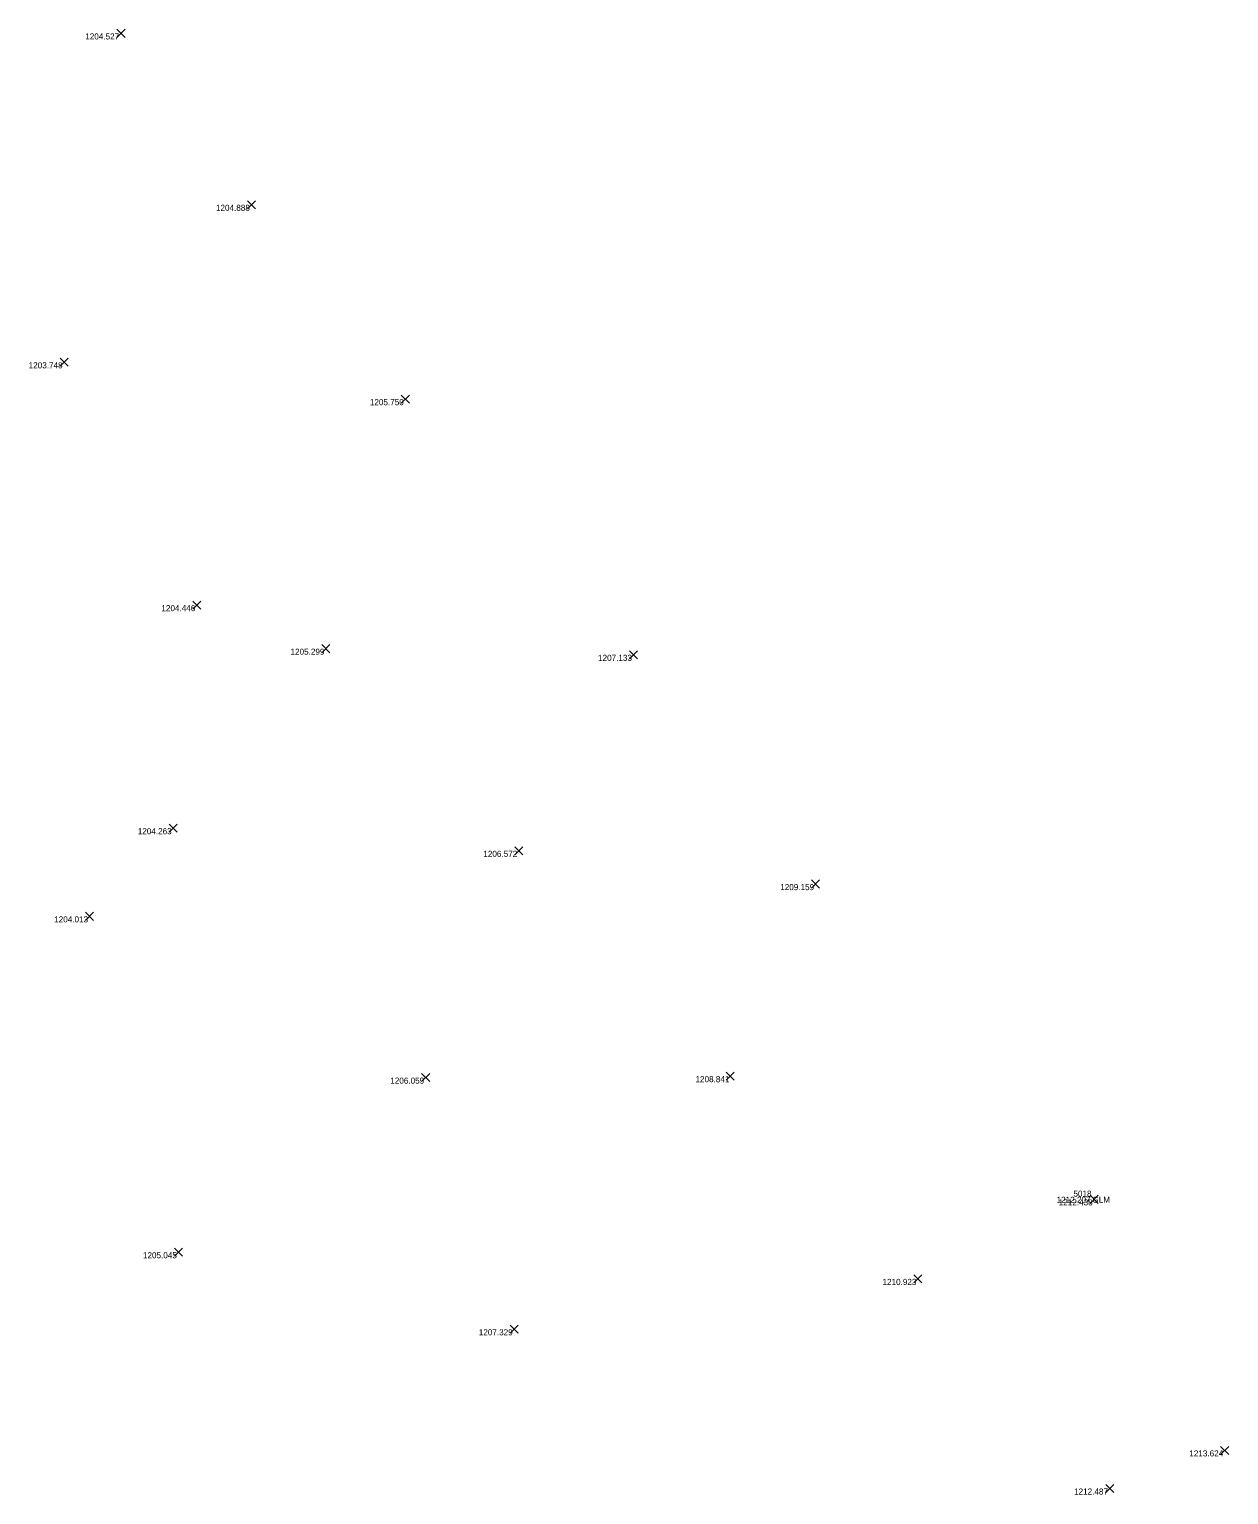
# Model space of a CAD drawing. Extents: x 2044997 to 2050342, y 455233 to 458054.
# Drawn here: x 2047746 to 2047943.2, y 457091.9 to 457332.8 of the extents above; entities that cross this region are included whole.
import ezdxf

# ---------------------------------------------------------------- set-up
doc = ezdxf.new("R2010")
doc.units = 0
for name, color, linetype in [('SV_X_Random_Point', 7, 'Continuous'), ('SV_X_Text_Comment', 7, 'Continuous'), ('SV_X_Text_Elevation', 7, 'Continuous'), ('SV_X_Text_Name', 7, 'Continuous')]:
    doc.layers.add(name, color=color, linetype=linetype)

msp = doc.modelspace()

# ---------------------------------------------------------------- linework, layer by layer
at = {"layer": 'SV_X_Random_Point'}
for p, q in [((2047760.38, 457331.47), (2047761.71, 457332.8)), ((2047760.38, 457332.8), (2047761.71, 457331.47)), ((2047781.82, 457303.29), (2047783.15, 457304.63)), ((2047781.82, 457304.63), (2047783.15, 457303.29)), ((2047751.03, 457277.4), (2047752.36, 457278.73)), ((2047751.03, 457278.73), (2047752.36, 457277.4)), ((2047807.12, 457271.34), (2047808.45, 457272.67)), ((2047807.12, 457272.67), (2047808.45, 457271.34)), ((2047772.85, 457237.48), (2047774.19, 457238.81)), ((2047772.85, 457238.81), (2047774.19, 457237.48)), ((2047794.06, 457230.32), (2047795.39, 457231.66)), ((2047794.06, 457231.66), (2047795.39, 457230.32)), ((2047844.63, 457229.31), (2047845.96, 457230.65)), ((2047844.63, 457230.65), (2047845.96, 457229.31)), ((2047768.95, 457200.81), (2047770.28, 457202.15)), ((2047768.95, 457202.15), (2047770.28, 457200.81)), ((2047825.78, 457197.09), (2047827.11, 457198.42)), ((2047825.78, 457198.42), (2047827.11, 457197.09)), ((2047874.57, 457191.62), (2047875.9, 457192.96)), ((2047874.57, 457192.96), (2047875.9, 457191.62)), ((2047755.21, 457186.32), (2047756.54, 457187.66)), ((2047755.21, 457187.66), (2047756.54, 457186.32)), ((2047810.46, 457159.81), (2047811.79, 457161.15)), ((2047810.46, 457161.15), (2047811.79, 457159.81)), ((2047860.54, 457160.06), (2047861.87, 457161.39)), ((2047860.54, 457161.39), (2047861.87, 457160.06)), ((2047920.38, 457139.8), (2047921.72, 457141.13)), ((2047920.38, 457141.13), (2047921.72, 457139.8)), ((2047769.83, 457131.11), (2047771.17, 457132.45)), ((2047769.83, 457132.45), (2047771.17, 457131.11)), ((2047891.4, 457126.72), (2047892.73, 457128.06)), ((2047891.4, 457128.06), (2047892.73, 457126.72)), ((2047825.01, 457118.44), (2047826.34, 457119.78)), ((2047825.01, 457119.78), (2047826.34, 457118.44)), ((2047941.82, 457098.53), (2047943.16, 457099.86)), ((2047941.82, 457099.86), (2047943.16, 457098.53)), ((2047922.94, 457092.26), (2047924.27, 457093.59)), ((2047922.94, 457093.59), (2047924.27, 457092.26))]:
    msp.add_line(p, q, dxfattribs=at)

# ---------------------------------------------------------------- texts
at = {"layer": 'SV_X_Text_Comment'}
msp.add_text('GLM', height=1, dxfattribs=at).set_placement((2047920.75, 457139.9))
at = {"layer": 'SV_X_Text_Elevation'}
for s, p in [('1204.527', (2047755.16, 457331.13)), ('1204.888', (2047776.65, 457302.96)), ('1203.748', (2047745.86, 457277.07)), ('1205.750', (2047801.95, 457271.01)), ('1204.446', (2047767.68, 457237.15)), ('1205.299', (2047788.91, 457229.99)), ('1207.133', (2047839.47, 457228.98)), ('1204.263', (2047763.79, 457200.48)), ('1206.572', (2047820.61, 457196.76)), ('1209.159', (2047869.42, 457191.29)), ('1204.013', (2047750.05, 457185.99)), ('1206.059', (2047805.31, 457159.48)), ('1208.841', (2047855.49, 457159.72)), ('1212.207', (2047914.87, 457139.9)), ('1212.438', (2047915.21, 457139.47)), ('1205.045', (2047764.65, 457130.78)), ('1210.923', (2047886.24, 457126.39)), ('1207.329', (2047819.86, 457118.11)), ('1213.624', (2047936.68, 457098.2)), ('1212.487', (2047917.73, 457091.93))]:
    msp.add_text(s, height=1, dxfattribs=at).set_placement(p)
at = {"layer": 'SV_X_Text_Name'}
msp.add_text('5018', height=1, dxfattribs=at).set_placement((2047917.63, 457140.9))

doc.saveas('drawing.dxf')
